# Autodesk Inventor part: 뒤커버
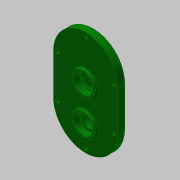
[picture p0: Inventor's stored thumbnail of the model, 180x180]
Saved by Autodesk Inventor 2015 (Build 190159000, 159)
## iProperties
Created: 2016-12
Part Number: 뒤커버
Material: 알루미늄 6061
Document SubType Name: Modeling
Designer: mduedu
Density: 2.71 g/cm^3
Mass: 236.429 g
Surface Area: 240.702 cm^2
Volume: 87.2433 cm^3
Appearance: 진녹색
Author: mduedu
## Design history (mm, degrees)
sketch "스케치1"
  geometry: L1 (40, -25)-(40, 25); L2 (-40, 25)-(-40, -25); L3 (-40, -25)-(40, 25); L4 (40, -25)-(-40, 25); A1 r 40 centre (0, 25) between (40, 25) and (-40, 25); A2 r 40 centre (0, -25) between (-40, -25) and (40, -25); 1 further point
  constraints: 8 end point, 4 point on circle, 4 tangent, 2 centre point, 2 midpoint, 1 parallel, 1 vertical
  dimensions: "d0" = 130 dimension on A2 A1; "d2" = 80 distance between parallel lines of L1 L2
extrude "돌출1" new body sketch "스케치1" distance "d3" = 10; taper "d4" = 0 deg
sketch "스케치2"
  geometry: C1 r 14 at (0, 11); 1 further point
  constraints: 1 centre point, 1 vertical alignment
  dimensions: "d5" = 28 diameter of C1; "d6" = 11 distance of C1.centre point (0, 0)
extrude "돌출2" join sketch "스케치2" distance "d7" = 3; taper "d8" = 0 deg
sketch "스케치3"
  geometry: C1 r 14 at (0, -33.1); C2 r 14 at (0, 11) reference; 1 further point
  constraints: 1 centre point, 1 vertical alignment
  dimensions: "d9" = 28 diameter of C1; "d69" = 44.1 distance of C1.centre C2.centre
extrude "돌출3" join sketch "스케치3" distance "d11" = 3; taper "d12" = 0 deg
hole "구멍1" diameter "d15" = 22; stored, may be unused: countersink angle "d19" = 90 deg, drill point angle "d21" = 0 deg; dims "d13" = 10, "d14" = 10, "d16" = 6, "d17" = 4, "d18" = 2, "d20" = 7
hole "구멍2" diameter "d24" = 18; stored, may be unused: countersink angle "d28" = 90 deg, drill point angle "d30" = 0 deg; dims "d22" = 10, "d23" = 10, "d25" = 6, "d26" = 4, "d27" = 2, "d29" = 1
hole "구멍3" diameter "d33" = 22; stored, may be unused: countersink angle "d37" = 90 deg, drill point angle "d39" = 0 deg; dims "d31" = 10, "d32" = 10, "d34" = 6, "d35" = 4, "d36" = 2, "d38" = 7
sketch "스케치4"
  geometry: C1 r 14 at (0, -33.1) reference; C2 r 18 at (0, -33.1); 1 further point
  constraints: 1 centre point, 1 coincident
  dimensions: "d40" = 36 diameter of C2
extrude "돌출4" join sketch "스케치4" distance "d41" = 4; taper "d42" = 0 deg
hole "구멍4" diameter "d45" = 22; stored, may be unused: countersink angle "d49" = 90 deg, drill point angle "d51" = 0 deg; dims "d43" = 10, "d44" = 10, "d46" = 6, "d47" = 4, "d48" = 2, "d50" = 7
hole "구멍5" diameter "d54" = 15; stored, may be unused: countersink angle "d58" = 90 deg, drill point angle "d60" = 0 deg; dims "d52" = 10, "d53" = 10, "d55" = 6, "d56" = 4, "d57" = 2, "d59" = 7
fillet "모깎기1" dims "d61" = 0.3
fillet "모깎기2" dims "d62" = 2
chamfer "모따기1" distance "d63" = 1; stored, may be unused: second distance "d64" = 2, angle "d65" = 45 deg
fillet "모깎기3" dims "d66" = 2
fillet "모깎기4" dims "d67" = 2
fillet "모깎기5" dims "d68" = 2
sketch "스케치5"
  geometry: L1 (-40, 25)-(-40, -25) reference; L2 (40, -25)-(40, 25) reference; L3 (35, 25)-(35, -25); L4 (-35, -25)-(-35, 25); A1 r 40 centre (0, 25) between (40, 25) and (-40, 25) reference; A2 r 40 centre (0, -25) between (-40, -25) and (40, -25) reference; A3 r 35 centre (0, 25) between (35, 25) and (-35, 25); A4 r 35 centre (0, -25) between (-35, -25) and (35, -25); 2 further points
  constraints: 5 point on circle, 4 end point, 2 centre point, 1 vertical alignment, 3 other
  dimensions: "d70" = 5 distance between parallel lines of L2 L3
sketch "스케치6"
  geometry: 1 further point
hole "구멍6" sketch "스케치6" at (0, 60) diameter "d71" = 4.5; stored, may be unused: countersink angle "d75" = 90 deg, drill point angle "d77" = 0 deg; dims "d72" = 6, "d73" = 8, "d74" = 4.6, "d76" = 8
node "솔리드1"
pattern_linear "직사각형 패턴1"
